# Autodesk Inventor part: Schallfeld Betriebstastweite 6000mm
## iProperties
Shininess: 20.0
Length Units: 11269
Angle Units: 11279
Time Units: 11290
Mass Units: 11283
Length Display Precision: 2
Angle Display Precision: 2
Category: Schallfelder
Part Number: Schallfeld Betriebstastweite 6000mm
Material: Lexan (klar)
Document SubType Name: Modellieren
Checked By: Alves
Created: 2005-08
Designer: Grube
Manufacturer: Standard
Standards Organization: Custom
Description: Schallfeld 6,0m
Density: 0.0
Volumn: 0.0
Area: 0.0
PropertySet Name: Model Information
Control State: 0
Master: False
Checked Out: False
Last Check In By: Kramp
Last Check In Date: 2005-08-11
ME: ST
Comments: keine Bemerkung
Title: Schallfelder
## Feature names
1. Blindzone_Aussenglocke [Revolution]
